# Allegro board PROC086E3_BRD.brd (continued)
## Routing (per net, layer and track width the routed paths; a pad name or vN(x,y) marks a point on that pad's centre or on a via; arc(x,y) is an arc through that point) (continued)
V3V3_OPTICAL: length 6
  TOP w0.381: MOD1.1 C46.1 L1.2
V5V0_HDMI1_CONN: length 6.9
  TOP w0.381: C6.1 v1(88.35,189.53) 88.35,189.07 v1(90.2,187.22)
  BOTTOM w0.254: J4.18 v1(88.35,189.53)
  BOTTOM w0.381: U34.13 v1(90.2,187.22)
VCC_1V8: length 7.5
  TOP w0.381: R54.1 39.55,159.19 v1(39.55,157.56) ; R69.1 46.7,154.88 v1(46.71,154.9) ; U9.2 v1(44.16,155.01) ; R68.1 v1(42.92,154.17)
  BOTTOM w0.381: v1(38.25,164.23) 38.25,165.08 38.52,165.35 FL23.1 ; R339.1 v1(36.91,164.2) ; U9.2 v1(44.16,155.01)
  vias: v1(94.63,79.87) v1(94.63,79.1) v1(95.64,79.87) v1(95.64,79.1)
VCC_3V3: length 174.6
  TOP w0.203: U7.18 v1(70.25,169.15) ; U7.7 65.85,169.19 v1(65.68,169.35) ; C43.1 30.2,156.2 30,156.4 30,157.9 U8.30 ; U5.7 47.72,172.76 v1(48.06,172.42) ; U7.24 72.65,168.92 72.85,169.12 v1(72.85,169.12) ; U15.23 v1(62.85,131.63) ; U7.1 63.45,168.79 v1(63.02,169.22) ; U7.30 70.65,174.9 v1(70.87,175.12) 71.05,174.94 U7.29 ; U6.7 54.54,169.05 v1(54.14,169.45) ; U3.13 v1(39.29,166.89) ; v1(65.21,130.03) 64.83,130.41 63.5,130.41 63.25,130.67 62.61,130.67 62.58,130.63 U15.21 ; U3.10 v1(38.09,169.42) ; U5.16 v1(50.8,168.02) ; U6.24 v1(62.07,168.02) ; U5.2 U5.3 49.32,172.52 v1(49.15,172.35) ; U4.16 v1(45.98,168.02) ; U6.18 58.94,169.04 v1(59.16,169.25) ; U6.1 v1(51.54,168.02) ; U3.16 v1(41.17,168.02)
  TOP w0.381: R20.1 v1(35.23,169.62) ; R206.1 v1(79.87,77.39) ; v1(63.25,133.21) 64.01,132.44 R103.1 ; R13.1 v1(13.64,180.42) ; FL4.2 29.87,172.84 C27.1 ; R264.1 v1(61.74,50.49) ; C27.1 v1(29.88,173.56) ; C27.1 v1(30.68,172.84) ; R248.1 v1(68.29,50.37) ; U17.16 C70.1 v1(72.38,115.73) ; v1(27.35,140.81) C45.1 26.52,140.34 26.2,140.03 U13.5 ; R32.1 76.12,163.66 75.54,163.66 v1(75.51,163.69) ; FL6.2 20.52,157.82 C40.1 C39.1 ; R251.1 79.86,48.45 v1(79.86,48.45) ; R62.1 28.26,155.33 v1(28.44,155.16) ; R7.2 21.56,187.4 21.95,187.02 v1(21.95,186.88) ; R249.1 v1(80.54,50.37) ; R310.1 R298.1 65.89,25.01 66.14,25.26 v1(66.14,27.49) ; R171.1 v1(42.93,103.39) ; v1(40.67,157.56) 40.67,158.69 R56.1 ; C43.1 C44.1 v1(31.24,154.24) ; R322.2 v1(85.25,177.12) ; FL2.1 C14.1 ; C14.1 v1(14.91,183.26) ; C14.1 v1(14.03,183.88) ; R208.1 v1(79.9,76.37) ; v1(69.92,48.4) C162.1 U30.8 ; v1(17.4,186.72) 18.08,187.4 R6.2 ; C39.1 v1(21.66,156.36) ; C39.1 v1(20.48,155.28) ; R64.1 32.03,153.45 v1(31.98,153.4) ; U14.1 C54.1 v1(46.69,127.38) ; C182.1 v1(66.32,46.62) ; C182.1 v1(67.18,47.43) ; C182.1 R267.2 ; R15.2 v1(32.33,176.73) ; v1(31.93,173.72) 31.93,173.72 R17.1 ; v1(65.21,128.89) 65.15,128.89 65.15,128.88 R110.1 ; R29.1 v1(98.4,166.84) ; R30.2 v1(21.68,165.5) ; v1(47.57,135.11) C48.1 46.7,133.89 C49.1 U14.24 U14.23 ; R8.2 v1(30.22,186.22) ; v1(69.83,109.55) C86.1 R152.2 ; R246.1 v1(80.53,51.64)
  BOTTOM w0.203: v1(75.51,163.69) 75.95,163.69 76.07,163.81 79.27,163.81 79.48,164.02 R338.2 ; 64.41,92.22 U21.8 ; R343.1 77.06,162.21 77.27,162.42 78.38,162.42 78.55,162.58 R341.1 ; U25.8 62.83,67.57
  BOTTOM w0.254: C263.1 65.51,152.79 66.25,153.53 U43.23 ; C262.1 67.97,152.36 67.25,153.08 U43.21
  BOTTOM w0.381: v1(38.23,147.05) 38.29,147.11 R357.2 ; U37.2 C222.1 v1(79.58,176.36) ; R347.1 v1(72.54,154.53) ; R354.1 67.73,149.27 68.05,149.59 v1(68.05,149.82) ; R364.2 v1(49.43,137.21) ; R360.2 37.78,145.97 v1(37.47,146.29) 37.4,146.35 R358.1 ; v1(48.56,152.23) 49,152.67 R350.1 ; v1(80.39,54.4) 80.51,54.28 R473.1 v1(81.57,55.19) ; v1(62.13,67.04) C136.1 62.83,67.57 ; FL25.1 C273.1 C271.1 ; 64.41,92.22 C109.1 v1(63.38,91.55) ; v1(52.83,143.75) 53.83,144.75 C268.1 ; v1(65.68,169.35) 65.85,169.19 U7.7 ; R376.1 R374.1 81.88,129.03 82.09,129.24 v1(82.09,129.8) ; v1(47.22,178.24) 47.21,178.23 R325.1 ; U45.5 51.99,144.49 v1(52.01,144.51) 52.32,144.82 C269.1 ; FL24.2 v1(42.45,165.3) ; FL15.1 C224.1 v1(74.4,173.36) ; v1(78.11,166.16) 78.13,166.14 R334.1 ; U6.18 58.94,169.04 v1(59.16,169.25) ; 77.28,160.85 77.06,161.07 R343.1 ; 77.28,160.85 R344.1 ; 77.28,160.85 77.06,160.64 R345.1 76.21,159.99 v1(75.79,160.41) ; R363.2 53.86,138.91 v1(53.24,139.53) ; U6.7 54.54,169.05 v1(54.14,169.45) ; U34.24 C213.1 v1(98.7,186.65) ; R352.2 v1(42.98,151.2) ; v1(70.71,152.79) 70.71,152.44 R348.1 ; C263.1 C266.1 v1(65.51,149.93) ; v1(65.55,170.3) C241.1 U39.5 ; R367.1 v1(32.52,134.02) ; v1(86.06,110.35) 85.92,110.48 R393.2 R394.2 ; C262.1 C265.1 67.31,150.63 v1(67.31,150.63) ; C271.1 v1(33.16,144.49) ; C271.1 v1(34.32,145.5) ; U4.16 v1(45.98,168.02) ; U7.18 v1(70.25,169.15) ; R356.2 69.8,149.31 69.8,149.31 v1(69.8,149.34) ; U3.16 v1(41.17,168.02) ; R333.1 v1(76.23,167.07) ; R491.2 v1(97.23,47.13) ; U5.16 v1(50.8,168.02) ; R485.2 v1(97.23,48.27)
  vias: v1(14.16,133.84) v1(14.16,132.82) v1(15.18,133.84) v1(15.18,132.82) v1(70.61,109.58) v1(77.66,171.31) v1(77.66,170.29) v1(78.68,171.31) v1(78.68,170.29) v1(98.48,45.91) v1(98.48,45.02) v1(99.36,45.91) v1(99.36,45.02) v1(100.25,45.91) v1(100.25,45.02)
VCC_5V0: length 20.8
  TOP w0.203: U11.17 v1(78.78,139.53) ; v1(63.22,141.82) 63.22,141.79 63.21,141.78 U10.17 ; U12.17 94.22,139.32 v1(94.42,139.11)
  TOP w0.381: C167.1 v1(63.21,52.37) ; C167.1 FL11.1 ; C167.1 v1(62.35,51.63) ; C220.1 v1(90.85,179.09) ; C77.1 v1(66.49,111.64) ; C77.1 v1(65.05,111.64) ; C77.1 FL8.1 ; FL9.1 C97.1 ; FL12.1 C195.1 ; C195.1 v1(65.05,37.33) ; C195.1 v1(64.02,37.99)
  BOTTOM w0.381: R319.1 v1(80.9,183.57) ; U10.17 63.21,141.78 63.22,141.79 v1(63.22,141.82) ; U34.11 v1(90.85,179.09) ; R327.2 v1(83.49,178.48) ; C275.1 94.6,139.29 v1(94.42,139.11) ; C274.1 v1(78.78,139.53) ; v1(77.14,184.79) 77.14,183.6 R320.1
  vias: v1(44.4,123.15) v1(45.42,123.15) v1(46.42,123.92) v1(46.43,123.15) v1(54.16,74.44) v1(54.18,73.67) v1(55.18,74.44) v1(55.19,73.67) v1(64.29,193.3) v1(65.18,193.3) v1(66.07,193.3) v1(66.07,192.54) v1(66.69,103.03) v1(66.69,102.14) v1(75.03,117.43) v1(75.03,116.42) v1(75.03,115.4) v1(75.03,114.38) v1(96.43,69.93) v1(96.43,69.17) v1(96.43,68.16) v1(97.32,69.93) v1(97.32,69.17) v1(97.32,68.16) v1(98.21,69.93) v1(98.21,69.17) v1(98.21,68.16)
VCC_12V:
  vias: v1(24.46,170.49) v1(24.46,169.48) v1(24.46,168.46) v1(25.22,170.49) v1(25.22,169.48) v1(25.22,168.46) v1(26.67,149.84) v1(26.67,148.83) v1(26.67,147.81) v1(27.69,149.84) v1(27.69,148.83) v1(27.69,147.81) v1(28.7,148.83) v1(28.7,147.81) v1(83.62,63.81) v1(83.62,62.92) v1(83.62,62.04) v1(84.63,63.81) v1(84.63,62.92) v1(84.63,62.04) v1(97.87,57.13) v1(97.87,56.24) v1(97.87,55.35) v1(98.88,57.13) v1(98.88,56.24) v1(98.88,55.35) v1(99.49,95.36) v1(99.49,94.47) v1(99.49,93.58) v1(100.51,95.36) v1(100.51,94.47) v1(100.51,93.58)
VCC_12V_CON:
  vias: v1(15.04,161.43) v1(15.04,160.41) v1(16.05,161.43) v1(16.05,160.41) v1(17.07,161.43) v1(17.07,160.41)
VCC_12V_FPD:
  vias: v1(7.28,176.07) v1(7.28,175.31) v1(8.29,176.07) v1(8.29,175.31) v1(9.31,176.07) v1(9.31,175.31) v1(10.33,176.07) v1(10.33,175.31)
VCC_CAM_3V3:
  vias: v1(73.28,179.56) v1(73.28,178.54) v1(73.28,177.53) v1(73.28,176.51)
VCC_CAM_5V0:
  vias: v1(65.29,194.81) v1(66.05,194.81) v1(71.93,186.29) v1(71.93,185.53) v1(72.69,186.29) v1(72.69,185.53)
VCC_CAM_IO: length 27
  TOP w0.203: U7.42 v1(65.85,172.69) ; U7.31 v1(70.25,172.69) ; U5.1 v1(50.8,173.82) ; U4.1 v1(45.98,173.82) ; U6.42 v1(54.54,172.69) ; U6.31 v1(58.94,172.69) ; U3.1 v1(41.17,173.82)
  TOP w0.381: v1(56.07,185.91) 56.07,183.69 55.57,183.19 R11.2 ; v1(44.96,184.7) 45.18,184.48 C15.1 v1(46.48,185.38)
  BOTTOM w0.203: 37.95,184.54 U35.8
  BOTTOM w0.381: U4.1 v1(45.98,173.82) ; U6.42 v1(54.54,172.69) ; C214.1 v1(39.84,184.54) ; C214.1 37.95,184.54 ; C214.1 v1(39.03,185.2) ; U7.42 v1(65.85,172.69) ; U6.31 v1(58.94,172.69) ; R317.1 v1(45.89,186.98) ; C15.1 v1(46.48,185.38) ; R313.1 42.27,187.28 v1(42.49,187.05) ; v1(41.92,178.41) FL14.1 43.32,178.41 v1(43.33,178.42) ; U3.1 v1(41.17,173.82) ; U5.1 v1(50.8,173.82) ; U7.31 v1(70.25,172.69) ; R316.1 v1(49.01,185.46)
  vias: v1(55.45,193.67) v1(56.46,193.67) v1(57.48,193.67) v1(58.5,193.67)
VCC_CAM_OSC: length 7.1
  BOTTOM w0.381: C216.1 R326.1 ; C216.1 39.73,180.8 39.35,180.42 U38.4 ; C216.1 C215.1 FL14.2
VCC_DIR: length 6.3
  BOTTOM w0.381: U45.24 C270.1 C272.1 FL25.2
VCCAD1_5V0: length 10.7
  TOP w0.254: C165.1 v1(56.35,51.71) 56.09,51.45 U32.49 ; U32.3 45.44,47.43 44.93,47.94
  TOP w0.381: C165.1 C166.1 C164.1 FL11.2 ; v1(42.24,47.94) C178.1 C179.1 44.93,47.94
VCCAD2_5V0: length 12.2
  TOP w0.254: v1(59.53,103.92) 59.06,104.39 U19.3 ; 48.08,101.44 U19.49
  TOP w0.381: FL9.2 C95.1 C93.1 59.72,103.13 C94.1 59.71,103.73 v1(59.53,103.92) ; 48.08,101.44 47.53,101.44 47.16,101.06 C102.1 C101.1 v1(44.94,99.97)
VCCDA1_5V0: length 28.3
  TOP w0.254: 44.93,41.77 45.1,41.93 U32.14 ; U32.34 59.01,41.43 59.37,41.07
  TOP w0.381: v1(44.9,40.33) C190.1 C188.1 44.8,41.64 44.93,41.77 ; FL12.2 C194.1 C192.1 C191.1 60.58,41 v1(60.52,41.07) 59.37,41.07
  BOTTOM w0.381: v1(60.52,41.07) 60.41,40.97 45.53,40.97 v1(44.9,40.33)
VCCDA2_5V0: length 11.2
  TOP w0.254: U19.14 59.51,109.89 v1(60.02,110.39) ; U19.34 45.73,110.39 45.22,110.89 C80.1
  TOP w0.381: v1(60.02,110.39) C83.1 C84.1 C82.1 FL8.2 ; C80.1 C79.1 v1(42.69,110.89)
VCCP_IN: length 40
  TOP w0.381: U29.8 C155.1 v1(31.54,55.04) ; v1(19.74,93.78) C107.1 20.19,93.08 20.69,92.57 U22.8 ; U23.8 C116.1 v1(31.54,87.96) ; v1(19.74,60.85) C149.1 20.22,60.16 20.73,59.65 U28.8 ; v1(31.54,65.64) C144.1 U27.8 ; U24.8 C328.1 v1(31.29,69.62) ; v1(31.54,98.57) C99.1 U20.8 ; v1(19.41,72.05) C334.1 U52.8
  BOTTOM w0.381: v1(31.54,92.78) C314.1 U48.8 ; U55.8 C357.1 v1(31.54,49.25) ; U54.8 20.72,55.25 20.21,54.74 C352.1 v1(19.74,54.04) ; U26.8 C141.1 v1(26.49,69.56) ; v1(14.61,71.97) C126.1 U51.8 ; U180.8 56.69,89.97 C766.1 v1(56.47,89.04) ; v1(19.74,86.97) C320.1 20.24,87.66 20.75,88.17 U49.8 ; U53.8 C344.1 v1(31.54,59.86) ; U179.8 C765.1 v1(39.5,39.32) ; U50.8 C325.1 v1(31.54,82.18)
  vias: v1(45.47,74.47) v1(45.46,73.57) v1(46.6,73.57) v1(47.61,73.57) v1(56.91,88.53)
VCCP_OUT: length 38.2
  TOP w0.381: v1(17.01,125.74) C58.1 U16.8 ; R268.1 v1(23.53,40.77) ; C85.1 23.95,106.63 v1(24.32,107) 24.42,107.1 24.42,111.94 24.8,112.32 C78.1 25.39,112.01 U18.8 ; U33.8 C201.1 17.01,27.43 17.27,27.18 v1(17.27,26.28) C203.1 ; R299.1 v1(24.91,24.26) ; v1(17.01,44.06) C175.1 U31.8 ; R286.1 v1(23.47,32.89) ; R250.1 v1(23.6,49.23) ; R139.1 v1(30.52,115.16) ; R105.1 v1(23.6,130.9) ; R153.1 v1(32.75,106.4) ; R127.1 v1(26.11,121.71)
  BOTTOM w0.381: R286.1 v1(23.47,32.89) ; v1(24.32,107) 24.14,106.82 C299.1 U47.8 ; R105.1 v1(23.6,130.9) ; R139.1 v1(30.52,115.16) ; v1(17.01,122.74) C285.1 U46.8 ; R268.1 v1(23.53,40.77) ; v1(17.14,41.06) C365.1 U56.8 ; v1(17.27,26.28) 17.01,26.02 C379.1 U57.8 ; R153.1 v1(32.75,106.4) ; R250.1 v1(23.6,49.23) ; R299.1 v1(24.91,24.26) ; R127.1 v1(26.11,121.71)
  vias: v1(36.61,124.05) v1(36.63,123.27) v1(37.63,124.05) v1(37.64,123.27)
VDD33_FPD: length 5.4
  TOP w0.203: U8.22 25.78,159.7 24.97,158.89 24.97,158.12 24.67,157.82 C41.1
  TOP w0.381: FL6.1 C41.1
VDD33_UB926: length 25.7
  TOP w0.203: U2.29 30.09,183.23 30.77,183.92 ; 19.49,182.73 U2.48
  TOP w0.381: FL2.2 C12.1 18.3,183.17 v1(18.67,182.8) 18.74,182.73 19.49,182.73 ; v1(34.11,184.12) C11.1 32.7,183.92 C13.1 30.77,183.92
  BOTTOM w0.381: v1(34.11,184.12) 33.54,183.55 20.88,183.55 20.13,182.8 v1(18.67,182.8)
VDD_3V3_CODEC1: length 32.3
  TOP w0.254: U32.12 v1(45.37,42.93) ; v1(59.84,47.43) U32.46
  TOP w0.381: v1(59.84,47.43) C181.1 C180.1 ; R277.2 v1(62.64,42.04) ; C180.1 R267.1 ; C180.1 62.67,46.53 v1(62.67,46.53) 62.67,46.52 R271.2
  BOTTOM w0.381: v1(59.84,47.43) 59.16,48.12 49.34,48.12 48.77,47.54 48.77,46.27 46.26,43.77 C369.1 v1(45.37,42.93) ; v1(62.67,46.53) 62.67,46.52 62.67,42.07 v1(62.64,42.04)
VDD_3V3_CODEC2: length 17.1
  TOP w0.254: U19.12 v1(59.3,108.89) ; U19.46 v1(45.32,104.39)
  TOP w0.381: v1(59.3,108.89) v1(60.57,108.89) C87.1 R152.1 ; R167.2 v1(42.8,104.25) ; v1(42.57,108.67) 42.8,108.44 R159.2
  BOTTOM w0.381: U19.46 v1(45.32,104.39) ; v1(60.57,108.89) 60.72,108.89 TP170.1 ; U19.12 v1(59.3,108.89)
VDD_CDCE: length 4.3
  BOTTOM w0.381: FL23.2 C253.1 39.2,163.35 C255.1 39.17,162.19 U42.3
VDDIO_UB926: length 11.3
  TOP w0.203: 27.08,175.15 U2.13 ; 25.97,187.54 24.64,186.2 24.64,185.28 24.58,185.22 U2.38 ; U2.24 28.96,180.7 30.42,180.7 31.28,179.84 C20.1
  TOP w0.381: C20.1 v1(31.88,180.71) ; C8.1 27.08,175.15 ; v1(26.8,188.9) 26.8,188.89 C9.1 25.97,187.54
  vias: v1(26.16,173.34) v1(26.92,173.34)
VDDOUT_CDCE: length 4.9
  BOTTOM w0.381: U42.6 U42.7 41.77,162.19 C254.1 41.8,163.35 C252.1 FL24.1
VINOUT_MUX_SEL0: length 160.1
  TOP w0.178: v1(70.78,142.48) U11.1 70.78,139.52 70.59,139.33 68.83,139.33 68.2,138.69 68.2,136.03 67.51,135.34 55.91,135.34 55.21,136.03 U10.1 ; U12.1 v1(86.22,141.79) ; J2.32 94.21,52.63 95.25,53.67 95.25,54.87 v1(94.77,55.35)
  L03_SIG1 w0.107: v1(94.77,55.35) 95.25,55.84 95.25,56.75 99.12,60.63 99.12,73.27 96.75,75.65 96.75,132.44 100.25,135.95 100.25,143.06 99.07,144.24 92.9,144.24 90.45,141.79 v1(86.22,141.79)
  BOTTOM w0.178: v1(86.22,141.79) 84.44,143.57 71.87,143.57 v1(70.78,142.48) U11.1
VINOUT_MUX_SEL1: length 162.1
  TOP w0.178: v1(86.11,149.28) 86.22,149.17 U12.56 ; v1(56.08,155.46) 55.21,154.59 U10.56 ; U11.56 70.78,149.17 v1(70.61,149.34) ; v1(94.64,54.64) 94.56,54.72 93.47,54.72 93.09,54.34 93.09,53.32 92.9,53.13 91.31,53.13 J2.34
  L03_SIG1 w0.107: v1(94.64,54.64) 95.73,54.64 95.89,54.8 95.89,56.95 99.5,60.57 99.5,73.35 97.08,75.78 97.08,132.27 100.61,135.8 100.61,143.21 98.48,145.35 87.02,145.35 86.11,146.26 v1(86.11,149.28) 80.34,149.28 79.96,148.9 79.6,148.9 79.17,149.34 v1(70.61,149.34)
  L08_SIG2 w0.107: v1(70.61,149.34) 70.3,149.03 70.3,148.98 70.13,148.8 61.8,148.8 56.08,154.52 v1(56.08,155.46)
  BOTTOM w0.178: R356.1 70.78,149.12 70.61,149.28 v1(70.61,149.34)
VINOUT_MUX_SEL2: length 44.3
  TOP w0.178: v1(70.71,150.38) 70.71,150.2 71.2,149.72 71.2,149.13 71.28,149.05 U11.55 ; U10.55 55.71,152.88 v1(57.1,154.26) ; v1(86.22,150.15) 86.66,149.7 86.66,148.21 U12.55
  L03_SIG1 w0.107: v1(86.22,150.15) 78.56,150.15 78.18,149.77 71.32,149.77 v1(70.71,150.38)
  L08_SIG2 w0.107: v1(70.71,150.38) 70.54,150.38 70.48,150.43 69.22,150.43 68.4,151.24 63.6,151.24 62.74,150.38 60.68,150.38 60.53,150.53 60.52,150.53 60.25,150.8 60.25,150.81 57.1,153.96 v1(57.1,154.26)
  BOTTOM w0.178: R348.2 70.71,150.85 v1(70.71,150.38)
AIN1_N: length 36.6
  TOP w0.254: U32.51 55.09,51.53 55.04,51.58 55.04,61.75 53.85,62.95 51.91,62.95 v1(51.61,63.25) 51.32,62.95 39.64,62.95 39.35,63.23 C146.2 38.82,63.25 37.67,63.25 R224.2 37.65,66.3 36.54,67.41 R220.2 34.45,67.41 R219.2
AIN1_P: length 36.3
  TOP w0.254: R234.2 33.76,58.03 R231.2 37.32,58.03 38.66,59.37 38.66,62.07 C146.1 39.35,62.25 39.64,62.54 51.32,62.54 v1(51.61,62.24) 51.91,62.54 53.68,62.54 54.64,61.58 54.64,51.58 54.59,51.53 U32.52
AIN2_N: length 41.3
  TOP w0.254: R236.2 34.39,56.7 R238.2 37.23,56.7 37.65,56.29 R242.2 C160.2 39.1,52.38 40.01,52.38 40.39,52.75 40.39,58.26 39.98,58.67 39.98,60.12 40.47,60.61 41.05,60.61 v1(41.35,60.91) 41.65,60.61 52.1,60.61 52.57,60.14 54.04,58.66 54.04,51.58 54.09,51.53 U32.53
AIN2_P: length 40.8
  TOP w0.254: U32.54 53.59,51.53 53.64,51.58 53.64,58.5 52.17,59.97 51.93,60.21 41.65,60.21 v1(41.35,59.91) 41.05,60.21 40.64,60.21 40.39,59.95 40.39,58.83 40.79,58.43 40.79,52.59 40.18,51.97 39.16,51.97 C160.1 38.84,49.11 37.16,47.43 R256.2 33.79,47.43 R257.2
AIN3_N: length 37.7
  TOP w0.254: v1(42.93,59.49) 43.22,59.19 51.74,59.19 53.04,57.89 53.04,51.58 53.09,51.53 U32.55
  BOTTOM w0.254: v1(42.93,59.49) 42.63,59.19 41.83,59.19 40.87,58.23 40.87,52.82 40.39,52.34 39.64,52.34 39.35,52.63 C355.2 R477.2 37.65,56.29 37.23,56.7 R471.2 33.79,56.7 R469.2
AIN3_P: length 35.7
  TOP w0.254: U32.56 52.59,51.53 52.64,51.58 52.64,57.72 51.57,58.78 43.22,58.78 v1(42.93,58.49)
  BOTTOM w0.254: R490.2 34.44,47.43 R489.2 37.16,47.43 38.84,49.11 C355.1 39.35,51.65 39.64,51.94 40.55,51.94 41.27,52.66 41.27,58.06 42,58.78 42.63,58.78 v1(42.93,58.49)
AIN4_N: length 33.7
  TOP w0.254: v1(46.13,58.09) 46.42,57.79 51.02,57.79 52.04,56.77 52.04,51.58 52.09,51.53 U32.57
  BOTTOM w0.254: v1(46.13,58.09) 45.83,57.79 44.93,57.79 44.68,58.05 44.68,62.15 43.88,62.95 39.64,62.95 39.35,63.23 C340.2 R459.2 37.65,66.3 36.54,67.41 R454.2 33.8,67.41 R453.2
AIN4_P: length 32.2
  TOP w0.254: U32.58 51.59,51.53 51.64,51.58 51.64,56.6 50.85,57.39 46.42,57.39 v1(46.13,57.09)
  BOTTOM w0.254: R468.2 34.41,58.03 R466.2 37.35,58.03 38.33,59.01 38.33,60.33 38.84,60.84 C340.1 39.35,62.25 39.64,62.54 43.72,62.54 44.27,61.98 44.27,57.88 44.76,57.39 45.83,57.39 v1(46.13,57.09)
AIN5_N: length 59.4
  TOP w0.254: U32.61 50.09,51.53 50.04,51.58 50.04,52.94 49.5,53.48 49.5,54.96 v1(49.8,55.25)
  BOTTOM w0.254: R447.2 16.96,79.82 R448.2 19.38,79.82 20.82,78.39 R445.2 20.85,75.41 C329.1 22.56,75.41 22.82,75.15 25.9,75.15 26.47,75.72 26.47,78.69 26.96,79.18 33.01,79.18 49.5,62.69 49.5,55.55 v1(49.8,55.25)
AIN5_P: length 58.3
  TOP w0.254: v1(48.79,55.25) 49.09,54.96 49.09,53.32 49.64,52.77 49.64,51.58 49.59,51.53 U32.62
  BOTTOM w0.254: R442.2 17.67,70.14 R441.2 21.04,70.14 22.02,71.13 C329.2 22.56,74.49 22.82,74.75 26.07,74.75 26.87,75.55 26.87,78.52 27.13,78.77 32.84,78.77 49.09,62.52 49.09,55.55 v1(48.79,55.25)
AIN6_N: length 40.2
  TOP w0.254: U32.63 49.09,51.53 49.04,51.58 49.04,52.35 47.42,53.97 47.42,54.95 v1(47.72,55.24)
  BOTTOM w0.254: R212.2 28.83,77.42 R211.2 31.35,77.42 31.67,77.1 R217.2 31.7,73.01 C140.1 33.42,73.01 33.68,72.75 36.96,72.75 47.42,62.29 47.42,55.54 v1(47.72,55.24)
AIN6_P: length 38.2
  TOP w0.254: v1(46.72,55.24) 47.02,54.95 47.02,53.81 48.64,52.18 48.64,51.58 48.59,51.53 U32.64
  BOTTOM w0.254: R221.2 29.55,67.74 R222.2 31.46,67.74 32.88,69.16 C140.2 33.42,72.09 33.68,72.35 36.79,72.35 47.02,62.12 47.02,55.54 v1(46.72,55.24)
AOUT1_A: length 5.5
  BOTTOM w0.381: R512.1 24.4,25.59 R511.2 24.4,28.39 C376.1 25.61,28.46 R517.2 26.76,28.43 R519.2
AOUT1_B: length 5.2
  BOTTOM w0.381: R515.1 22.81,29.52 R518.2 24.43,29.34 C376.2 24.5,29.41 R517.1 26.74,29.41 R516.2
AOUT1_C: length 6.1
  BOTTOM w0.381: U57.2 18.99,27.19 19.59,26.59 C374.1 23.41,26.59 R511.1
AOUT1_D: length 5.4
  BOTTOM w0.381: U57.3 19.64,27.57 19.99,27.22 21.45,27.22 21.83,27.6 C377.1 21.87,28.5 R518.1
AOUT1_E: length 3.5
  BOTTOM w0.381: R510.2 R513.1 R515.2 C377.2
AOUT1_N: length 36.7
  TOP w0.254: U32.32 56.09,37.83 56.04,37.79 56.04,33.48 47.44,24.87 44.24,24.87 v1(43.94,24.58)
  BOTTOM w0.254: v1(43.94,24.58) 43.64,24.87 36.96,24.87 33.12,28.71 32.05,28.71 31.8,28.46 31.8,28.17 31.54,27.92 C378.2
AOUT1_O: length 11.9
  BOTTOM w0.381: R514.1 17.79,31.62 18.34,31.07 U57.1 18.34,26.37 19.04,25.67 C374.2 23.34,25.67 R512.2
AOUT1_P: length 36
  TOP w0.254: U32.31 55.59,37.83 55.64,37.79 55.64,33.65 47.27,25.28 44.24,25.28 v1(43.94,25.58)
  BOTTOM w0.254: C375.2 31.54,29.91 31.8,29.66 31.8,29.37 32.05,29.12 33.29,29.12 37.13,25.28 43.64,25.28 v1(43.94,25.58)
AOUT1N: length 1.4
  BOTTOM w0.381: C378.1 28.59,28.3 R519.1
AOUT1P: length 1.4
  BOTTOM w0.381: R516.1 28.59,29.53 C375.1
AOUT2_A: length 8.3
  BOTTOM w0.381: R530.1 19.86,20 R529.2 24.43,20.07 C383.1 25.61,20.03 R527.1 26.76,20 R531.2
AOUT2_B: length 5
  BOTTOM w0.381: R528.2 22.1,20.98 R524.1 23.3,20.95 C383.2 24.5,20.98 R527.2 26.76,20.98 R525.2
AOUT2_C: length 3.2
  BOTTOM w0.381: R529.1 19.93,21.94 C381.1 19.64,22.23 U57.6
AOUT2_D: length 3.5
  BOTTOM w0.381: U57.5 20.29,23.18 21.13,22.34 C384.1 21.17,22.02 R528.1
AOUT2_E: length 3.6
  BOTTOM w0.381: C384.2 22.14,21.96 R524.2 R523.1 R521.2
AOUT2_N: length 38.1
  TOP w0.254: v1(35.33,19.99) 35.63,20.29 37.2,20.29 38.12,21.21 38.12,25.36 39.03,26.27 47.18,26.27 55.04,34.13 55.04,37.79 55.09,37.83 U32.30
  BOTTOM w0.254: C385.2 31.54,19.49 31.8,19.75 31.8,20.04 32.05,20.29 35.03,20.29 v1(35.33,19.99)
AOUT2_O: length 5
  BOTTOM w0.381: U57.7 18.99,22.23 C381.2 18.7,21.94 R530.2 R526.1
AOUT2_P: length 37.4
  TOP w0.254: U32.29 54.59,37.83 54.64,37.79 54.64,34.3 47.02,26.68 38.86,26.68 37.71,25.53 37.71,21.38 37.03,20.7 35.63,20.7 v1(35.33,20.99)
  BOTTOM w0.254: v1(35.33,20.99) 35.03,20.7 32.05,20.7 31.8,20.95 31.8,21.24 31.54,21.49 C382.2
AOUT2N: length 1.4
  BOTTOM w0.381: R531.1 28.59,19.88 C385.1
AOUT2P: length 1.4
  BOTTOM w0.381: C382.1 28.59,21.11 R525.1
AOUT3_A: length 8.9
  TOP w0.381: R309.2 26.76,20 R306.1 24.5,20 C208.1 24.44,20 R308.2 R307.1
AOUT3_B: length 5
  TOP w0.381: R305.2 22.1,20.98 R302.1 24.44,20.98 C208.2 24.5,20.98 R306.2 26.76,20.98 R303.2
AOUT3_C: length 3.3
  TOP w0.381: R308.1 19.28,21.94 C205.1 18.99,22.23 U33.2
AOUT3_D: length 4.1
  TOP w0.381: R305.1 21.17,22.02 C207.1 20.5,22.06 19.64,22.91 U33.3
AOUT3_E: length 3.6
  TOP w0.381: R299.2 R301.1 R302.2 22.14,21.96 C207.2
AOUT3_N: length 37.2
  TOP w0.254: C209.2 31.54,19.49 31.8,19.75 31.8,20.04 32.05,20.29 32.99,20.29 33.99,21.29 33.99,23.2 v1(34.28,23.5) 33.99,23.8 33.99,26.17 35.2,27.39 46.84,27.39 54.04,34.59 54.04,37.79 54.09,37.83 U32.28
AOUT3_O: length 4.4
  TOP w0.381: U33.1 18.34,22.23 C205.2 18.05,21.94 R307.2 R304.1
AOUT3_P: length 36.5
  TOP w0.254: U32.27 53.59,37.83 53.64,37.79 53.64,34.76 46.67,27.8 35.04,27.8 33.58,26.34 33.58,23.8 v1(33.28,23.5) 33.58,23.2 33.58,21.46 32.82,20.7 32.05,20.7 31.8,20.95 31.8,21.24 31.54,21.49 C206.2
AOUT3N: length 1.4
  TOP w0.381: R309.1 28.59,19.88 C209.1
AOUT3P: length 1.4
  TOP w0.381: R303.1 28.59,21.11 C206.1
AOUT4_A: length 5.5
  TOP w0.381: R287.1 24.4,25.59 R288.2 24.4,28.39 C200.1 25.61,28.46 R294.1 26.76,28.43 R295.2
AOUT4_B: length 5.2
  TOP w0.381: R291.1 22.81,29.52 R293.2 24.43,29.34 C200.2 24.5,29.41 R294.2 26.74,29.41 R292.2
AOUT4_C: length 5.4
  TOP w0.381: U33.6 19.64,27.24 20.29,26.59 C197.1 23.41,26.59 R288.1
AOUT4_D: length 2.7
  TOP w0.381: U33.5 21.8,28.43 C199.1 21.87,28.5 R293.1
AOUT4_E: length 3.5
  TOP w0.381: C199.2 R291.2 R289.1 R286.2
AOUT4_N: length 29.6
  TOP w0.254: U32.26 53.09,37.83 53.04,37.79 53.04,34.99 46.77,28.71 42.31,28.71 v1(42.01,28.42) 41.71,28.71 32.05,28.71 31.8,28.46 31.8,28.17 31.54,27.92 C202.2
AOUT4_O: length 11.7
  TOP w0.381: R290.1 18.25,31.62 18.99,30.88 U33.7 18.99,26.64 19.96,25.67 C197.2 23.34,25.67 R287.2
AOUT4_P: length 29
  TOP w0.254: C198.2 31.54,29.91 31.8,29.66 31.8,29.37 32.05,29.12 41.71,29.12 v1(42.01,29.42) 42.31,29.12 46.6,29.12 52.64,35.16 52.64,37.79 52.59,37.83 U32.25
AOUT4N: length 1.4
  TOP w0.381: C202.1 28.59,28.3 R295.1
AOUT4P: length 1.4
  TOP w0.381: R292.1 28.59,29.53 C198.1
AOUT5_A: length 5.5
  BOTTOM w0.381: R496.2 26.76,44.76 R494.1 25.61,44.79 C362.1 24.4,44.72 R483.2 24.4,41.91 R484.1
AOUT5_B: length 5.2
  BOTTOM w0.381: R492.1 22.81,45.86 R495.2 24.43,45.67 C362.2 25.61,45.71 R494.2 26.74,45.74 R493.2
AOUT5_C: length 6.2
  BOTTOM w0.381: U56.2 18.99,43.48 19.56,42.91 C360.1 23.41,42.91 R483.1
AOUT5_D: length 5.4
  BOTTOM w0.381: R495.1 22.96,44.79 C363.1 21.83,43.96 21.42,43.55 19.92,43.55 19.64,43.82 U56.3
AOUT5_E: length 3.5
  BOTTOM w0.381: C363.2 R492.2 R487.1 R482.2
AOUT5_N: length 40.5
  TOP w0.254: U32.24 52.09,37.83 52.04,37.79 52.04,35.39 47.03,30.37 39.79,30.37 v1(39.5,30.08)
  BOTTOM w0.254: C364.2 31.54,44.25 31.8,44.51 31.8,44.79 32.05,45.05 34.67,45.05 37.09,42.63 37.09,31.15 37.86,30.37 39.2,30.37 v1(39.5,30.08)
AOUT5_O: length 11.9
  BOTTOM w0.381: R488.1 17.81,47.96 18.34,47.43 U56.1 18.34,42.73 19.08,41.99 C360.2 23.34,41.99 R484.2
AOUT5_P: length 39.8
  TOP w0.254: v1(39.5,31.08) 39.79,30.78 46.86,30.78 51.64,35.56 51.64,37.79 51.59,37.83 U32.23
  BOTTOM w0.254: C361.2 31.54,46.25 31.8,46 31.8,45.71 32.05,45.45 34.84,45.45 37.5,42.8 37.5,31.31 38.03,30.78 39.2,30.78 v1(39.5,31.08)
AOUT5N: length 1.4
  BOTTOM w0.381: R496.1 28.59,44.63 C364.1
AOUT5P: length 1.4
  BOTTOM w0.381: C361.1 28.59,45.87 R493.1
AOUT6_A: length 8.3
  BOTTOM w0.381: R509.2 26.76,36.34 R505.1 25.61,36.37 C370.1 24.43,36.41 R507.2 19.86,36.34 R508.1
AOUT6_B: length 5.2
  BOTTOM w0.381: R506.2 21.95,37.32 R502.1 23.27,37.32 23.3,37.29 C370.2 24.5,37.32 R505.2 26.76,37.32 R503.2
AOUT6_C: length 3.2
  BOTTOM w0.381: R507.1 19.93,38.27 C367.1 19.64,38.57 U56.6
AOUT6_D: length 3.5
  BOTTOM w0.381: U56.5 20.29,39.08 C371.1 20.94,37.23 R506.1
AOUT6_E: length 3.8
  BOTTOM w0.381: R499.2 R501.1 21.86,39.57 C371.2 21.99,38.3 R502.2
AOUT6_N: length 28.3
  TOP w0.254: U32.22 51.09,37.83 51.04,37.79 51.04,35.72 47.73,32.41 38.57,32.41 36.66,34.31 35.54,34.31 v1(35.24,34.01)
  BOTTOM w0.254: v1(35.24,34.01) 34.95,34.31 33.82,34.31 33.32,34.8 33.32,36.3 32.95,36.68 32.11,36.68 31.8,36.37 31.8,36.08 31.54,35.83 C372.2
AOUT6_O: length 5
  BOTTOM w0.381: U56.7 18.99,38.57 C367.2 18.7,38.27 R508.2 R504.1
AOUT6_P: length 27.6
  TOP w0.254: v1(35.24,35.01) 35.54,34.72 36.83,34.72 38.74,32.81 47.56,32.81 50.64,35.89 50.64,37.79 50.59,37.83 U32.21
  BOTTOM w0.254: C368.2 31.54,37.83 31.8,37.57 31.8,37.34 32.05,37.09 33.11,37.09 33.73,36.47 33.73,34.97 33.99,34.72 34.95,34.72 v1(35.24,35.01)
AOUT6N: length 1.4
  BOTTOM w0.381: C372.1 28.59,36.21 R509.1
AOUT6P: length 1.4
  BOTTOM w0.381: R503.1 28.59,37.44 C368.1
AOUT7_A: length 8.9
  TOP w0.381: R283.1 18.12,36.41 R284.2 19.32,36.37 C187.1 24.5,36.34 R282.1 26.76,36.34 R285.2
AOUT7_B: length 5.2
  TOP w0.381: R279.2 26.76,37.32 R282.2 24.5,37.32 C187.2 24.44,37.32 R275.1 23.13,37.19 R281.2
AOUT7_C: length 3.2
  TOP w0.381: R284.1 19.28,38.27 C184.1 18.99,38.57 U31.2
AOUT7_D: length 4.2
  TOP w0.381: R281.1 20.94,37.23 C186.1 20.21,38.42 19.64,38.99 U31.3
AOUT7_E: length 3.8
  TOP w0.381: R275.2 23.13,38.42 C186.2 21.89,38.45 R273.1 R268.2
AOUT7_N: length 23.9
  TOP w0.254: C189.2 31.54,35.83 31.8,36.08 31.8,36.37 32.05,36.62 37.13,36.62 38.66,35.1 42.17,35.1 v1(42.47,34.8) 42.77,35.1 48.86,35.1 50.04,36.29 50.04,37.79 50.09,37.83 U32.20
AOUT7_O: length 4.4
  TOP w0.381: R280.1 R283.2 18.05,38.27 C184.2 18.34,38.57 U31.1
AOUT7_P: length 23.2
  TOP w0.254: C185.2 31.54,37.83 31.8,37.57 31.8,37.28 32.05,37.03 37.3,37.03 38.82,35.5 42.17,35.5 v1(42.47,35.8) 42.77,35.5 48.69,35.5 49.64,36.45 49.64,37.79 49.59,37.83 U32.19
AOUT7N: length 1.4
  TOP w0.381: R285.1 28.59,36.21 C189.1
AOUT7P: length 1.4
  TOP w0.381: C185.1 28.59,37.44 R279.1
AOUT8_A: length 5.5
  TOP w0.381: R265.2 26.76,44.76 R262.1 25.61,44.79 C173.1 24.4,44.72 R253.2 24.4,41.91 R252.1
AOUT8_B: length 5.2
  TOP w0.381: R259.2 26.74,45.74 R262.2 25.61,45.71 C173.2 24.43,45.67 R261.2 22.81,45.86 R258.1
AOUT8_C: length 5.5
  TOP w0.381: U31.6 19.64,43.42 20.15,42.91 C169.1 23.41,42.91 R253.1
AOUT8_D: length 2.7
  TOP w0.381: R261.1 22.96,44.79 C172.1 21.8,44.76 U31.5
AOUT8_E: length 3.5
  TOP w0.381: C172.2 R258.2 R254.1 R250.2
AOUT8_N: length 28.6
  TOP w0.254: U32.18 49.09,37.83 49.04,37.79 49.04,36.97 48.55,36.48 39.83,36.48 38.2,38.11 38.2,44.59 37.74,45.05 37.38,45.05 v1(37.08,44.75) 36.79,45.05 32.05,45.05 31.8,44.79 31.8,44.51 31.54,44.25 C177.2
AOUT8_O: length 11.8
  TOP w0.381: R252.2 23.34,41.99 C169.2 19.58,41.99 18.99,42.58 U31.7 18.99,47.08 18.12,47.96 R255.1
AOUT8_P: length 27.9
  TOP w0.254: U32.17 48.59,37.83 48.64,37.79 48.64,37.14 48.38,36.89 40,36.89 38.61,38.28 38.61,44.76 37.91,45.45 37.38,45.45 v1(37.08,45.75) 36.79,45.45 32.05,45.45 31.8,45.71 31.8,46 31.54,46.25 C170.2
AOUT8N: length 1.4
  TOP w0.381: C177.1 28.59,44.63 R265.1
AOUT8P: length 1.4
  TOP w0.381: C170.1 28.59,45.87 R259.1
APP_BD_PORZ: length 4.1
  BOTTOM w0.178: J17.76 84.97,46.97 83.7,48.24 R486.1
AUD_REFCLK1_BUF: length 2.6
  TOP w0.178: R122.2 50.01,126.4 50.11,126.5 U14.4
AUDEXP_INTB: length 98.6
  TOP w0.178: v1(80.82,49.13) 81.72,49.13 82.23,48.63 J2.15 ; U15.22 R103.2 65.19,131.13 v1(65.21,131.11)
  L08_SIG2 w0.107: v1(80.82,49.13) 80.82,49.59 81.38,50.15 81.38,51.62 79.69,53.31 79.69,55.1 82.11,57.51 82.11,96.13 71.4,106.84 71.4,121.17 65.71,126.86 65.71,130.62 v1(65.21,131.11)
AUDEXP_P16: length 2.9
  TOP w0.178: U15.16 v1(60.28,128.1)
  BOTTOM w0.178: v1(60.28,128.1) 60.66,127.72 TP54.1
AUDIO_EXT_REFCLK1: length 63.2
  TOP w0.178: J1.26 v1(92.41,100.51) ; R122.1 v1(50.01,123.95)
  BOTTOM w0.178: v1(92.41,100.51) 90.73,102.19 90.73,113.93 86.33,118.32 70.56,118.32 69.93,118.96 69.93,122.72 68.83,123.81 56.03,123.81 55.63,123.4 50.56,123.4 v1(50.01,123.95)
BIN1_N: length 23.1
  TOP w0.254: R172.2 34.44,100.39 R173.2 37.01,100.39 37.65,99.75 R179.2 C104.2 39.35,96.17 39.64,95.89 40.71,95.89 41.96,97.14 45.17,97.14 v1(45.47,97.44) 45.76,97.14 47.37,97.14 49.64,99.41 49.64,100.24 49.59,100.29 U19.51
BIN1_P: length 24.5
  TOP w0.254: R186.2 33.79,90.99 R184.2 38.36,90.99 38.84,91.47 C104.1 39.35,95.19 39.64,95.48 40.88,95.48 42.13,96.73 45.17,96.73 v1(45.47,96.43) 45.76,96.73 47.54,96.73 50.04,99.24 50.04,100.24 50.09,100.29 U19.52
BIN2_N: length 33.9
  TOP w0.254: R189.2 34.41,89.79 R191.2 36.87,89.79 37.65,89.02 R198.2 C120.2 39.35,85.57 39.64,85.28 40,85.28 40.25,85.53 40.25,87.15 39.42,87.98 39.42,88.51 v1(39.12,88.81) 39.42,89.1 39.42,89.78 40.59,90.95 40.59,93.38 41.77,94.56 46.63,94.56 50.61,98.54 50.61,101.42 U19.53
BIN2_P: length 34.7
  TOP w0.254: U19.54 51.09,100.71 51.07,100.69 51.07,100.42 51.02,100.37 51.02,98.37 46.8,94.15 41.94,94.15 41,93.21 41,90.78 39.83,89.61 39.83,89.1 v1(40.12,88.81) 39.83,88.51 39.83,88.15 40.66,87.32 40.66,85.36 40.17,84.87 39.64,84.87 39.35,84.59 C120.1 38.84,82.13 37.05,80.34 R203.2 33.79,80.34 R204.2
BIN3_N: length 34.9
  TOP w0.254: v1(43.18,93.12) 43.48,92.82 46.61,92.82 51.64,97.85 51.64,100.24 51.59,100.29 U19.55
  BOTTOM w0.254: v1(43.18,93.12) 42.88,92.82 41.49,92.82 41,92.33 41,85.66 40.56,85.23 39.18,85.23 C323.2 R439.2 37.65,89.02 36.77,89.89 R431.2 33.74,89.89 R429.2
BIN3_P: length 34.3
  TOP w0.254: U19.56 52.09,100.29 52.04,100.24 52.04,97.68 46.78,92.41 43.48,92.41 v1(43.18,92.12)
  BOTTOM w0.254: R444.2 34.44,80.34 R443.2 37.01,80.34 38.85,82.18 38.85,84.57 C323.1 39.08,84.82 40.73,84.82 41.4,85.49 41.4,92.16 41.66,92.41 42.88,92.41 v1(43.18,92.12)
BIN4_N: length 34.1
  TOP w0.254: v1(45.91,91.55) 45.93,91.55 46.22,91.26 46.89,91.26 52.64,97.01 52.64,100.24 52.59,100.29 U19.57
  BOTTOM w0.254: v1(45.91,91.55) 45.61,91.25 44.98,91.25 44.73,91.5 44.73,95.15 43.98,95.89 39.63,95.89 39.35,96.17 C308.2 R422.2 37.65,99.75 36.96,100.44 R417.2 33.85,100.44 R416.2
BIN4_P: length 33.7
  TOP w0.254: U19.58 53.09,100.29 53.04,100.24 53.04,96.84 47.06,90.85 46.22,90.85 45.92,90.55 45.92,90.53 v1(45.91,90.53)
  BOTTOM w0.254: R428.2 34.44,91.04 R426.2 37.59,91.04 38.31,91.76 38.31,92.51 38.84,93.05 C308.1 39.35,95.19 39.65,95.49 43.81,95.49 44.32,94.98 44.32,91.33 44.82,90.84 45.61,90.84 v1(45.91,90.53)
BIN5_N: length 63.3
  TOP w0.254: U19.61 54.59,100.29 54.64,100.24 54.64,90.93 53.42,89.72 45.06,89.72 42.21,86.87 42.21,80.57 40.85,79.21 24.7,79.21 23.98,78.48 23.98,77.12 v1(23.68,76.83) 23.98,76.53 23.98,75.41 23.72,75.15 22.82,75.15 22.56,75.41 C335.1 20.85,75.41 R452.2 20.82,79.07 20.13,79.75 R455.2 18.36,79.75 R456.2
BIN5_P: length 64.3
  TOP w0.254: U19.62 55.09,100.29 55.04,100.24 55.04,90.77 53.59,89.31 45.23,89.31 42.62,86.7 42.62,80.4 41.02,78.8 24.87,78.8 24.38,78.32 24.38,77.12 v1(24.68,76.83) 24.38,76.53 24.38,75.24 23.89,74.75 22.82,74.75 22.56,74.49 C335.2 22.02,71.28 20.96,70.21 R451.2 17.88,70.21 R450.2
BIN6_N: length 53.7
  TOP w0.254: U19.63 55.59,100.29 55.64,100.24 55.64,90.19 53.64,88.2 46.59,88.2 44.48,86.08 44.48,79.51 40.84,75.88 40.84,75.08 v1(40.55,74.79) 40.84,74.49 40.84,73.42 40.18,72.75 34.83,72.75 34.57,73.01 C125.1 32.91,73.01 R205.2 32.88,76.68 32.21,77.35 R202.2 30.23,77.35 R201.2
BIN6_P: length 54.3
  TOP w0.254: R209.2 29.75,67.81 R207.2 32.4,67.81 34.09,69.5 C125.2 34.57,72.09 34.83,72.35 40.35,72.35 41.25,73.25 41.25,74.49 v1(41.55,74.79) 41.25,75.08 41.25,75.71 44.88,79.34 44.88,85.91 46.76,87.79 53.81,87.79 56.04,90.02 56.04,100.24 56.09,100.29 U19.64
BISTEN: length 2.4
  TOP w0.178: R7.1 21.4,186.42 21.58,186.24 U2.44
BOUT1_A: length 5.6
  BOTTOM w0.381: R403.2 33.8,110.7 R401.1 32.66,110.73 C295.1 31.45,110.66 R395.2 31.45,107.71 R396.1
BOUT1_B: length 5.2
  BOTTOM w0.381: R400.2 33.79,111.68 R401.2 31.55,111.68 C295.2 31.48,111.61 R402.2 29.86,111.8 R399.1
BOUT1_C: length 6.3
  BOTTOM w0.381: U47.2 26.04,109.34 26.67,108.71 C292.1 30.45,108.71 R395.1
BOUT1_D: length 5.5
  BOTTOM w0.381: U47.3 26.69,109.74 26.97,109.45 28.5,109.45 28.88,109.84 C296.1 28.92,110.77 R402.1
BOUT1_E: length 3.5
  BOTTOM w0.381: C296.2 R399.2 R397.1 R392.2
BOUT1_N: length 14.9
  TOP w0.254: U19.32 48.59,113.71 48.27,114.03 42.14,114.03 v1(41.85,113.73)
  BOTTOM w0.254: v1(41.85,113.73) 41.55,114.03 40.54,114.03 40.18,113.67 40.18,111.54 39.63,110.98 38.61,110.98 C297.2
BOUT1_O: length 20.1
  BOTTOM w0.381: R398.1 17.58,113.07 19.05,114.54 24.46,114.54 25.39,113.61 U47.1 25.39,108.57 26.17,107.79 C292.2 30.38,107.79 R396.2
BOUT1_P: length 15.6
  TOP w0.254: v1(41.85,114.73) 42.14,114.44 48.44,114.44 49.09,113.79 U19.31
  BOTTOM w0.254: C294.2 38.61,111.39 39.46,111.39 39.78,111.71 39.78,113.84 40.37,114.44 41.55,114.44 v1(41.85,114.73)
BOUT1N: length 1.4
  BOTTOM w0.381: R403.1 35.64,110.57 C297.1
BOUT1P: length 1.4
  BOTTOM w0.381: C294.1 35.64,111.8 R400.1
BOUT2_A: length 9.1
  BOTTOM w0.381: R415.2 34.57,102.12 R410.1 33.42,102.15 C304.1 27.02,102.15 R413.2 25.82,102.19 R414.1
BOUT2_B: length 4.9
  BOTTOM w0.381: R409.2 34.57,103.1 R410.2 32.31,103.1 C304.2 32.25,103.1 R408.1 30.03,103.1 R411.2
BOUT2_C: length 3.4
  BOTTOM w0.381: U47.6 26.69,105.14 26.83,105.01 C300.1 26.83,103.19 R413.1
BOUT2_D: length 4.4
  BOTTOM w0.381: U47.5 27.34,105.3 28.43,104.21 C305.1 29.06,104.17 R411.1
BOUT2_E: length 3.5
  BOTTOM w0.381: C305.2 30.07,104.08 R408.2 R407.1 R405.2
BOUT2_N: length 24.7
  TOP w0.254: U19.30 49.59,113.99 49.64,114.03 49.64,114.29 48.56,115.36 45.13,115.36 v1(44.83,115.07)
  BOTTOM w0.254: C306.2 39.37,102.41 40.28,102.41 40.77,102.9 40.77,110.4 42.99,112.62 42.99,115.04 43.31,115.36 44.53,115.36 v1(44.83,115.07)
BOUT2_O: length 12.5
  BOTTOM w0.381: R412.1 18.82,102.43 19.49,103.1 R414.2 25.91,103.26 C300.2 25.91,105 26.04,105.14 U47.7
BOUT2_P: length 25.4
  TOP w0.254: U19.29 50.09,113.99 50.04,114.03 50.04,114.45 48.73,115.77 45.13,115.77 v1(44.83,116.07)
  BOTTOM w0.254: v1(44.83,116.07) 44.53,115.77 43.14,115.77 42.58,115.21 42.58,112.79 40.36,110.57 40.36,103.06 40.11,102.82 39.37,102.82 C302.2
BOUT2N: length 1.4
  BOTTOM w0.381: R415.1 36.4,102 C306.1
BOUT2P: length 1.4
  BOTTOM w0.381: R409.1 36.4,103.23 C302.1
BOUT3_A: length 9.7
  TOP w0.381: R170.2 34.57,102.12 R164.1 33.42,102.15 C92.1 32.24,102.19 R169.2 25.17,102.19 R168.1
BOUT3_B: length 4.9
  TOP w0.381: R163.2 30.03,103.1 R160.1 32.25,103.1 C92.2 33.42,103.07 R164.2 34.57,103.1 R162.2
BOUT3_C: length 3.4
  TOP w0.381: U18.2 26.04,105.1 26.18,104.96 C88.1 26.18,103.19 R169.1
BOUT3_D: length 5.1
  TOP w0.381: U18.3 26.69,105.24 27.72,104.21 C91.1 29.06,104.17 R163.1
BOUT3_E: length 3.5
  TOP w0.381: R153.2 R156.1 R160.2 30.07,104.08 C91.2
BOUT3_N: length 30.1
  TOP w0.254: U19.28 50.59,113.99 50.64,114.03 50.64,114.63 48.66,116.61 42.14,116.61 41.24,115.71 41.24,110.27 39.32,108.35 39.32,107.74 v1(39.61,107.44) 39.32,107.15 39.32,106.18 39.72,105.77 40.08,105.77 40.88,104.98 40.88,102.9 40.39,102.41 39.86,102.41 39.61,102.16 39.61,101.87 39.35,101.62 C96.2
BOUT3_O: length 11.8
  TOP w0.381: U18.1 25.39,105.16 25.26,105.02 C88.2 25.26,103.26 R168.2 25.1,103.11 19.49,103.11 18.82,102.43 R165.1
BOUT3_P: length 30.8
  TOP w0.254: C90.2 39.35,103.61 39.61,103.36 39.61,103.07 39.86,102.82 40.22,102.82 40.47,103.07 40.47,104.81 39.91,105.37 39.55,105.37 38.91,106.01 38.91,107.15 v1(38.61,107.44) 38.91,107.74 38.91,108.51 40.83,110.43 40.83,115.87 41.97,117.01 48.83,117.01 51.04,114.8 51.04,114.03 51.09,113.99 U19.27
BOUT3N: length 1.4
  TOP w0.381: C96.1 36.4,102 R170.1
BOUT3P: length 1.4
  TOP w0.381: R162.1 36.4,103.23 C90.1
BOUT4_A: length 5.6
  TOP w0.381: R140.1 31.45,107.71 R141.2 31.45,110.66 C76.1 32.66,110.73 R149.1 33.8,110.7 R150.2
BOUT4_B: length 5.2
  TOP w0.381: R147.2 33.79,111.68 R149.2 32.66,111.65 C76.2 31.48,111.61 R148.2 29.86,111.8 R145.1
BOUT4_C: length 5.6
  TOP w0.381: U18.6 26.69,109.3 27.28,108.71 C71.1 30.45,108.71 R141.1
BOUT4_D: length 2.7
  TOP w0.381: U18.5 28.85,110.7 C75.1 30.01,110.73 R148.1
BOUT4_E: length 3.5
  TOP w0.381: C75.2 R145.2 R142.1 R139.2
BOUT4_N: length 24.2
  TOP w0.254: U19.26 51.59,113.99 51.64,114.03 51.64,115.16 49.3,117.5 40.49,117.5 39.73,116.73 39.73,115.32 v1(40.02,115.03) 39.73,114.73 39.73,113.55 40.12,113.16 40.12,111.48 39.63,110.98 39.1,110.98 38.84,110.73 38.84,110.44 38.59,110.19 C81.2
BOUT4_O: length 20.4
  TOP w0.381: R143.1 17.59,113.07 19.06,114.54 25.55,114.54 26.04,114.05 U18.7 26.04,108.48 26.72,107.79 C71.2 30.38,107.79 R140.2
BOUT4_P: length 24.9
  TOP w0.254: U19.25 52.09,113.99 52.04,114.03 52.04,115.32 49.47,117.9 40.32,117.9 39.32,116.9 39.32,115.32 v1(39.02,115.03) 39.32,114.73 39.32,113.38 39.71,112.99 39.71,111.64 39.46,111.39 39.1,111.39 38.84,111.64 38.84,111.93 38.59,112.19 C73.2
BOUT4N: length 1.4
  TOP w0.381: C81.1 35.64,110.57 R150.1
BOUT4P: length 1.4
  TOP w0.381: C73.1 35.64,111.8 R147.1
BOUT5_A: length 5.5
  BOTTOM w0.381: R379.2 26.76,126.44 R377.1 25.61,126.47 C282.1 24.4,126.4 R369.2 24.4,123.55 R370.1
BOUT5_B: length 5.2
  BOTTOM w0.381: R375.2 26.74,127.42 R377.2 25.61,127.39 C282.2 24.43,127.35 R378.2 22.81,127.54 R373.1
BOUT5_C: length 6.2
  BOTTOM w0.381: R369.1 23.41,124.56 C280.1 19.54,124.56 18.99,125.11 U46.2
BOUT5_D: length 5.4
  BOTTOM w0.381: R378.1 22.96,126.47 C283.1 21.83,125.57 21.56,125.3 19.9,125.3 19.64,125.55 U46.3
BOUT5_E: length 3.5
  BOTTOM w0.381: C283.2 R373.2 R371.1 R368.2
BOUT5_N: length 34.8
  TOP w0.254: U19.24 52.59,113.99 52.64,114.03 52.64,115.68 49.87,118.45 39.54,118.45 38.67,117.58 36.94,117.58 v1(36.66,117.31)
  BOTTOM w0.254: v1(36.66,117.31) 36.38,117.58 35.75,117.58 35.26,118.08 35.26,124.96 33.49,126.73 32.05,126.73 31.8,126.47 31.8,126.18 31.54,125.93 C284.2
BOUT5_O: length 12
  BOTTOM w0.381: R372.1 17.87,129.63 18.34,129.16 U46.1 18.34,124.31 19.01,123.64 C280.2 23.34,123.64 R370.2
BOUT5_P: length 35.5
  TOP w0.254: U19.23 53.09,113.99 53.04,114.03 53.04,115.85 50.04,118.85 39.37,118.85 38.5,117.99 36.98,117.99 v1(36.66,118.31)
  BOTTOM w0.254: v1(36.66,118.31) 36.34,117.99 35.92,117.99 35.66,118.25 35.66,125.13 33.66,127.13 32.05,127.13 31.8,127.39 31.8,127.67 31.54,127.93 C281.2
BOUT5N: length 1.4
  BOTTOM w0.381: C284.1 28.59,126.31 R379.1
BOUT5P: length 1.4
  BOTTOM w0.381: C281.1 28.59,127.55 R375.1
BOUT6_A: length 8.3
  BOTTOM w0.381: R390.1 18.77,118.08 R389.2 24.43,118.08 C289.1 25.6,118.04 R387.1 26.69,118.08 R391.2
BOUT6_B: length 4.9
  BOTTOM w0.381: R385.2 26.69,118.92 R387.2 24.51,118.92 C289.2 24.44,118.99 R384.1 22.18,118.99 R388.2
BOUT6_C: length 3.2
  BOTTOM w0.381: R389.1 19.78,119.08 C287.1 19.78,120.75 19.64,120.88 U46.6
BOUT6_D: length 3.5
  BOTTOM w0.381: U46.5 20.29,121.05 C290.1 21.28,120.06 R388.1
BOUT6_E: length 3.8
  BOTTOM w0.381: C290.2 22.29,119.97 R384.2 23.9,119.97 R383.1 R381.2
BOUT6_N: length 28.7
  TOP w0.254: U19.22 53.59,113.99 53.64,114.03 53.64,116.08 50.38,119.34 36.47,119.34 35.44,118.3 34.39,118.3 v1(34.09,118)
  BOTTOM w0.254: v1(34.09,118) 33.8,118.3 32.05,118.3 31.8,118.05 31.8,117.76 31.54,117.51 C291.2
BOUT6_O: length 5
  BOTTOM w0.381: U46.7 18.99,120.98 18.86,120.84 C287.2 18.86,119.15 R390.2 R386.1
BOUT6_P: length 29.3
  TOP w0.254: U19.21 54.09,113.99 54.04,114.03 54.04,116.25 50.55,119.74 36.31,119.74 35.27,118.71 34.39,118.71 v1(34.09,119.01)
  BOTTOM w0.254: C288.2 31.54,119.5 31.8,119.25 31.8,118.96 32.05,118.71 33.8,118.71 v1(34.09,119.01)
BOUT6N: length 1.4
  BOTTOM w0.381: C291.1 28.59,117.89 R391.1
BOUT6P: length 1.4
  BOTTOM w0.381: R385.1 28.59,119.12 C288.1
BOUT7_A: length 8.9
  TOP w0.381: R136.1 18.12,118.08 R137.2 24.43,118.08 C68.1 25.61,118.04 R135.1 26.76,118.01 R138.2
BOUT7_B: length 4.9
  TOP w0.381: R134.2 22.18,118.99 R131.1 24.44,118.99 C68.2 25.61,118.96 R135.2 26.76,118.99 R132.2
BOUT7_C: length 3.2
  TOP w0.381: R137.1 19.13,119.08 C65.1 19.13,120.76 18.99,120.9 U16.2
BOUT7_D: length 4.2
  TOP w0.381: U16.3 19.64,121.06 20.6,120.1 C67.1 21.28,120.06 R134.1
BOUT7_E: length 3.8
  TOP w0.381: C67.2 22.29,119.97 R131.2 23.9,119.97 R129.1 R127.2
BOUT7_N: length 31.4
  TOP w0.254: C69.2 31.54,117.51 31.8,117.76 31.8,118.05 32.05,118.3 32.66,118.3 33.18,118.81 33.18,119.97 33.43,120.23 33.79,120.23 v1(34.09,119.93) 34.38,120.23 51.12,120.23 54.64,116.71 54.64,114.03 54.59,113.99 U19.20
BOUT7_O: length 4.4
  TOP w0.381: U16.1 18.34,120.98 18.21,120.84 C65.2 18.18,120.08 18.18,119.12 R136.2 R133.1
BOUT7_P: length 32.1
  TOP w0.254: C66.2 31.54,119.5 31.8,119.25 31.8,118.96 32.05,118.71 32.5,118.71 32.77,118.98 32.77,120.14 33.26,120.63 33.79,120.63 v1(34.09,120.93) 34.38,120.63 51.29,120.63 55.04,116.88 55.04,114.03 55.09,113.99 U19.19
BOUT7N: length 1.4
  TOP w0.381: R138.1 28.59,117.89 C69.1
BOUT7P: length 1.4
  TOP w0.381: C66.1 28.59,119.12 R132.1
BOUT8_A: length 5.5
  TOP w0.381: R117.2 26.76,126.44 R115.1 25.61,126.47 C57.1 24.4,126.4 R107.2 24.4,123.55 R106.1
BOUT8_B: length 5.2
  TOP w0.381: R111.1 23,128.38 R114.2 24.43,127.35 C57.2 25.61,127.39 R115.2 26.74,127.42 R113.2
BOUT8_C: length 5.6
  TOP w0.381: U16.6 19.64,124.94 20.03,124.56 C53.1 23.41,124.56 R107.1
BOUT8_D: length 4.8
  TOP w0.381: U16.5 20.29,125.52 20.56,125.25 21.52,125.25 21.83,125.57 C56.1 22.96,126.47 R114.1
BOUT8_E: length 3.5
  TOP w0.381: R105.2 R108.1 R111.2 C56.2
BOUT8_N: length 36.4
  TOP w0.254: U19.18 55.59,113.99 55.64,114.03 55.64,117.13 51.09,121.67 33.53,121.67 32.97,122.23 32.97,123.05 v1(32.67,123.35) 32.97,123.65 32.97,126.46 32.7,126.73 32.05,126.73 31.8,126.47 31.8,126.18 31.54,125.93 C59.2
BOUT8_O: length 12.1
  TOP w0.381: R109.1 18.46,129.63 19,129.09 19,126.45 U16.7 18.99,124.23 19.58,123.64 C53.2 23.34,123.64 R106.2
BOUT8_P: length 37
  TOP w0.254: U19.17 56.09,113.99 56.04,114.03 56.04,117.29 51.26,122.08 33.7,122.08 33.38,122.4 33.38,123.05 v1(33.67,123.35) 33.38,123.65 33.38,126.62 32.87,127.13 32.05,127.13 31.8,127.39 31.8,127.67 31.54,127.93 C55.2
BOUT8N: length 1.4
  TOP w0.381: R117.1 28.59,126.31 C59.1
BOUT8P: length 1.4
  TOP w0.381: C55.1 28.59,127.55 R113.1
BUF_VPFE0_DATA0: length 16.3
  TOP w0.178: U6.2 v1(52.54,169.15) ; U6.13 56.94,166.3 v1(57.37,165.88) R37.2
  L08_SIG2 w0.107: v1(52.54,169.15) 52.3,168.91 52.3,168.69 52.39,168.59 53.37,168.59 53.47,168.5 53.47,168.37 53.37,168.27 52.39,168.27 52.3,168.18 52.3,168.05 52.39,167.95 53.37,167.95 53.47,167.86 53.47,167.73 53.37,167.63 52.39,167.63 52.3,167.54 52.3,166.81 52.73,166.38 56.87,166.38 v1(57.37,165.88)
BUF_VPFE0_DATA1: length 16.3
  TOP w0.178: U6.14 57.34,166.66 58.13,165.88 v1(58.61,165.88) R38.2 ; U6.3 v1(52.94,166.89)
  L08_SIG2 w0.107: v1(58.61,165.88) 58.13,165.88 57.02,166.99 57.02,168.52 56.93,168.61 56.79,168.61 56.7,168.52 56.7,166.99 56.61,166.89 56.33,166.89 56.23,166.99 56.23,167.99 56.14,168.08 56.01,168.08 55.91,167.99 55.91,166.99 55.82,166.89 v1(52.94,166.89)
BUF_VPFE0_DATA2: length 16.3
  TOP w0.178: R33.2 v1(52.39,165.88) 52.89,165.88 53.74,166.73 U6.5
  TOP w0.203: U6.16 v1(58.14,166.89)
  L03_SIG1 w0.107: v1(58.14,166.89) 58.14,168.43 57.99,168.59 53.47,168.59 53.37,168.48 53.37,167.83 53.26,167.72 53.07,167.72 52.97,167.82 52.97,168.49 52.88,168.59 52.6,168.59 52.39,168.37 v1(52.39,165.88)
BUF_VPFE0_DATA3: length 16.2
  TOP w0.178: U6.6 54.14,166.39 v1(53.63,165.88) R34.2 ; v1(58.39,169.48) 58.54,169.33 U6.17
  L03_SIG1 w0.107: v1(58.39,169.48) 58.67,169.2 58.67,166.61 58.47,166.4 55.64,166.4 55.54,166.5 55.54,166.79 55.45,166.89 55.32,166.89 55.22,166.79 55.22,166.5 55.13,166.4 54.89,166.4 54.79,166.5 54.79,167.55 54.7,167.65 54.57,167.65 54.47,167.55 54.47,166.5 54.38,166.4 53.75,166.4 53.63,166.29 v1(53.63,165.88)
BUF_VPFE0_DATA4: length 16.3
  TOP w0.178: R39.2 v1(59.86,165.88) 59.34,166.39 U6.19 ; U6.8 54.94,169.67 v1(54.14,170.47)
  L03_SIG1 w0.107: v1(54.14,170.47) 54.6,170.01 54.82,170.01 54.92,169.92 54.92,169.6 55.01,169.5 55.16,169.5 55.27,169.61 55.27,169.9 55.38,170.01 59.18,170.01 59.66,169.53 59.66,166.07 v1(59.86,165.88)
BUF_VPFE0_DATA5: length 16.2
  TOP w0.178: v1(56.14,170.49) 55.34,169.69 U6.9 ; R40.2 v1(61.1,165.88) 60.75,165.88 59.74,166.88 U6.20
  L03_SIG1 w0.107: v1(56.14,170.49) 60.76,170.49 61.54,169.71 61.54,166.32 v1(61.1,165.88)
BUF_VPFE0_DATA6: length 16.2
  TOP w0.178: v1(60.78,166.68) 60.54,166.92 U6.22 ; U6.11 56.14,167.15 v1(54.88,165.88) R35.2
  L08_SIG2 w0.107: v1(54.88,165.88) 54.88,164.36 55.07,164.17 55.29,164.17 55.39,164.26 55.39,164.81 55.48,164.91 55.61,164.91 55.71,164.81 55.71,164.26 55.8,164.17 55.93,164.17 56.03,164.26 56.03,164.81 56.12,164.91 56.25,164.91 56.35,164.81 56.35,164.26 56.44,164.17 58.8,164.17 60.5,165.87 60.5,166.4 v1(60.78,166.68)
BUF_VPFE0_DATA7: length 16.3
  TOP w0.178: U6.12 56.54,166.3 v1(56.12,165.88) R36.2
  TOP w0.203: U6.23 v1(60.94,169.15)
  L08_SIG2 w0.107: v1(56.12,165.88) 56.12,165.53 56.31,165.34 59,165.34 59.28,165.62 59.28,166.81 59.38,166.91 60.16,166.91 60.25,167 60.25,167.13 60.16,167.23 59.38,167.23 59.28,167.32 59.28,167.45 59.38,167.55 60.16,167.55 60.25,167.64 60.25,167.77 60.16,167.87 59.38,167.87 59.28,167.96 59.28,168.18 59.49,168.38 60.78,168.38 60.94,168.55 v1(60.94,169.15)
BUF_VPFE0_DATA8: length 16.3
  TOP w0.178: R45.2 v1(70.26,165.13) 69.67,165.72 68.83,165.72 68.25,166.31 U7.13 ; U7.2 v1(63.85,169.15)
  BOTTOM w0.178: v1(70.26,165.13) 69.67,164.55 69.09,164.55 68.44,165.2 68.44,166.77 67.92,167.29 64.67,167.29 63.85,168.11 v1(63.85,169.15)
BUF_VPFE0_DATA9: length 16.2
  TOP w0.178: U7.3 64.25,167 64.47,166.78 v1(64.52,166.78) ; R46.2 v1(71.42,165.16) 70.42,166.16 69.02,166.16 68.65,166.54 U7.14
  L08_SIG2 w0.107: v1(64.52,166.78) 64.36,166.63 64.36,165.36 64.67,165.06 66.14,165.06 66.7,165.62 70.97,165.62 v1(71.42,165.16)
BUF_VPFE0_DATA10: length 16.3
  TOP w0.178: U7.16 69.45,166.89 v1(69.34,166.79) ; U7.5 65.05,166.55 64.57,166.07 v1(63.86,166.07) 63.2,165.41 R41.2
  L08_SIG2 w0.107: v1(69.34,166.79) 69.34,168.16 69.11,168.38 65.16,168.38 65.05,168.28 65.05,167.61 64.94,167.5 64.72,167.5 64.63,167.6 64.63,168.29 64.53,168.38 64.04,168.38 63.86,168.2 v1(63.86,166.07)
BUF_VPFE0_DATA11: length 16.3
  TOP w0.178: v1(70.21,166.71) 69.85,167.07 U7.17 ; U7.6 65.45,166.24 v1(64.87,165.67) 64.36,165.16 R42.2
  L08_SIG2 w0.107: v1(64.87,165.67) 65.57,166.37 65.57,167.3 65.67,167.39 65.8,167.39 65.89,167.3 65.89,166.37 65.99,166.28 66.12,166.28 66.21,166.37 66.21,167.3 66.31,167.39 66.44,167.39 66.53,167.3 66.53,166.37 66.63,166.28 66.85,166.28 66.94,166.37 66.94,166.98 67.06,167.1 67.41,167.1 67.51,166.99 67.51,166.38 67.62,166.28 69.77,166.28 v1(70.21,166.71)
BUF_VPFE0_DATA12: length 3.5
  TOP w0.178: R532.2 65.53,165.72 66.25,166.43 U7.8
BUF_VPFE0_DATA13: length 3.2
  TOP w0.178: U7.9 66.65,166.38 66.75,166.28 R533.2
BUF_VPFE0_HD: length 19.7
  TOP w0.178: v1(71.53,166.73) 71.85,167.05 U7.22 71.85,169.8 71.56,170.09 68.12,170.09 67.45,169.41 U7.11 ; R43.2 67.92,165.01 v1(67.82,165.11)
  L03_SIG1 w0.107: v1(71.53,166.73) 70.66,167.6 68.17,167.6 67.87,167.29 67.05,167.29 66.95,167.2 66.95,167.07 67.05,166.97 67.72,166.97 67.82,166.88 67.82,166.75 67.72,166.65 67.05,166.65 66.95,166.56 66.95,166.43 67.05,166.33 67.72,166.33 67.82,166.24 v1(67.82,165.11)
BUF_VPFE0_PCLK: length 16.3
  TOP w0.178: U5.11 48.12,169.13 48.26,169.27 48.77,169.27 48.92,169.12 U5.13 48.92,166.22 48.28,165.59 46.74,165.59 46.58,165.43 46.58,165.21 46.74,165.06 48.76,165.06 48.92,164.9 48.92,164.68 48.76,164.52 46.74,164.52 46.58,164.37 46.58,164.15 46.74,163.99 48.76,163.99 48.92,163.83 R31.2
BUF_VPFE0_VD: length 12
  TOP w0.178: R44.2 72.64,166.33 72.25,166.72 U7.23 72.25,169.59 v1(72.42,169.76) ; U7.12 67.85,168.95 v1(68.17,169.27)
  L03_SIG1 w0.107: v1(68.17,169.27) 68.17,169.72 68.49,170.04 72.14,170.04 v1(72.42,169.76)
C_FPD_DOUT_N: length 2.7
  TOP w0.102: C36.1 arc(24.64,161.21) 25.22,161.1 26.44,161.1 arc(26.58,161.12) U8.19
C_FPD_DOUT_P: length 2.7
  TOP w0.102: U8.20 arc(26.6,160.77) 26.48,160.79 25.18,160.79 arc(24.62,160.68) C37.1
C_FPD_RIN_N: length 3.1
  TOP w0.102: U2.50 arc(20.13,181.8) 20.01,181.82 18.18,181.82 arc(17.68,181.72) C17.1
C_FPD_RIN_P: length 3.1
  TOP w0.102: U2.49 arc(20.12,182.15) 19.98,182.13 18.21,182.13 arc(17.68,182.23) C16.1
CAM_EXT_CLK: length 5.4
  BOTTOM w0.178: U38.3 37.7,180.39 37.25,180.84 U35.2 37.25,182.54 36.25,183.54 U35.5
CAM_I2C_SCL: length 43.3
  TOP w0.178: v1(57.33,180.07) 56.62,180.78 56.62,186.19 55.83,186.98 v1(46.87,186.98) 46.29,187.56 31.69,187.56 29.39,189.86 26.8,189.86 J3.14
  BOTTOM w0.178: U36.3 47.13,185.52 46.87,185.78 R317.2 v1(46.87,186.98) ; J6.29 57.57,180.31 v1(57.33,180.07)
CAM_I2C_SDA: length 38.1
  TOP w0.178: J3.12 28.74,191.05 31.8,187.99 v1(48.03,187.99) 55.45,187.99 57.32,186.13 v1(58.07,186.13)
  BOTTOM w0.178: J6.30 57.07,185.13 v1(58.07,186.13) ; v1(48.03,187.99) R316.2 48.03,185.81 47.78,185.55 U36.4
CAM_LI_EXT_CLK: length 40.8
  BOTTOM w0.178: J6.7 68.57,176.04 67.03,174.51 49.43,174.51 46.53,177.4 36.5,177.4 36.24,177.67 R323.2
CAM_OV_EXT_CLK: length 20.1
  TOP w0.178: J3.20 19.56,189.48 29.14,189.48 31.66,186.95 v1(35.51,186.95)
  BOTTOM w0.178: R315.2 36.28,186.95 v1(35.51,186.95)
CAM_SEL_LI#: length 38.3
  TOP w0.178: U6.48 v1(51.66,173.82) 51.66,172.17 49.72,170.22 U5.15 v1(49.72,166.89) ; U7.48 v1(62.96,173.82) ; U4.14 U4.15 v1(44.9,166.89) 44.9,166.25 44.63,165.97 40.51,165.97 40.09,166.39 U3.15
  L08_SIG2 w0.107: v1(62.96,173.82) 62.15,174.63 61.21,174.63 60.4,173.82 v1(51.66,173.82)
  BOTTOM w0.178: v1(44.9,166.89) 44.9,166.31 45.21,166 49.53,166 49.72,166.18 v1(49.72,166.89) ; U39.4 63.38,173.41 v1(62.96,173.82)
CAM_SEL_OV#: length 120.6
  TOP w0.178: J1.91 83.36,122.01 81.92,123.45 81.92,127.03 82.63,127.74 82.63,135.38 84.81,137.56 84.81,153.91 84.25,154.47 74.35,154.47 73.53,155.28 v1(73.53,156.83) ; U7.25 72.65,172.22 72.21,171.79 63.86,171.79 v1(61.83,173.82) U6.25 ; U5.14 49.32,169.61 v1(48.9,170.04) 48.49,170.44 40.18,170.44 39.69,169.95 U3.14
  L03_SIG1 w0.107: v1(48.9,170.04) 50.24,171.38 61.01,171.38 61.83,172.2 v1(61.83,173.82)
  L08_SIG2 w0.107: v1(73.53,156.83) 73.53,169.71 72.29,170.95 v1(61.98,170.95)
  BOTTOM w0.178: U39.2 v1(61.98,170.95) 61.98,173.67 v1(61.83,173.82)
CAM_VIO_SEL: length 186.1
  TOP w0.178: U1.1 v1(62.85,192.98) ; v1(71.68,177.58) 71.68,176.65 73.38,174.95 73.38,161.7 v1(72.8,161.12) ; J2.20 v1(93.68,49.63)
  L03_SIG1 w0.107: v1(71.68,177.58) 71.68,184.36 67.46,188.58 63.4,188.58 62.85,189.12 v1(62.85,192.98)
  L08_SIG2 w0.107: v1(93.68,49.63) 90.14,53.17 90.14,92.02 91.03,92.91 91.03,104.35 95.05,108.36 95.05,122.77 94.18,123.63 94.18,130.4 87.2,137.38 87.2,141.82 84.2,144.81 65.81,144.81 64.85,145.78 64.85,146.77 66.52,148.45 70.46,148.45 71.22,149.21 71.22,159.55 v1(72.8,161.12)
